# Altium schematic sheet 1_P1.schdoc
size 309 x 223 mm; Symbol: Sheet-Symbol_A4; Device: Sheet-Symbol_A4; Company: 嘉立创EDA; Version: V1.0; Page Size: A4; @Project Name: piezoAmpBoard; @Page Count: 1; @Update Date: 2024-03-09; @Create Date: 2024-03-08; @Schematic Name: Schematic1; @Page No: 1; @Page Name: P1; @Board Name: Board1; @Create Time: 23:16:16; @Update Time: 13:11:04
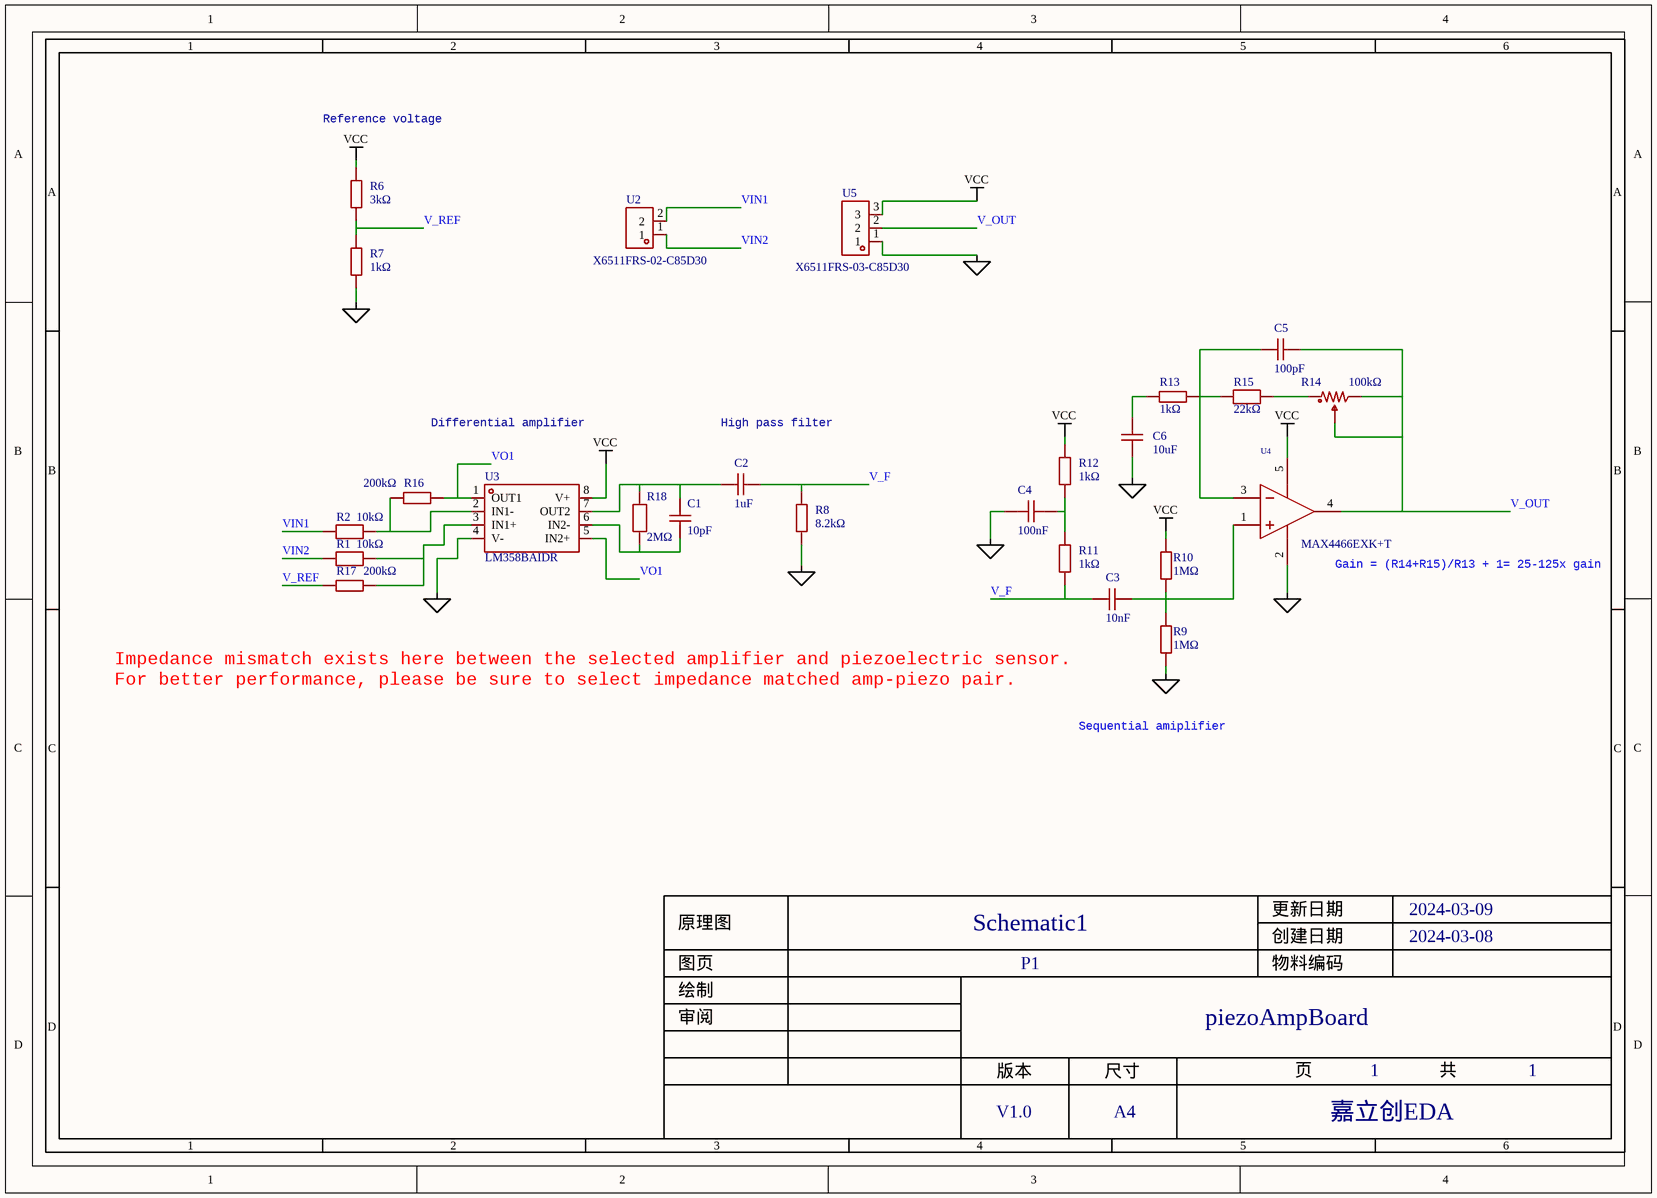
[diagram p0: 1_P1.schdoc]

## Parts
C1  10pF  [C0402]  (value not drawn)
C2  1uF  [C0402]  (value not drawn)
C3  10nF  [C0402]  (value not drawn)
C4  100nF  [C0402]  (value not drawn)
C5  100pF  [C0402]  (value not drawn)
C6  10uF  [C0402]  (value not drawn)
R1  10kΩ  [R0201]  (value not drawn)
R2  10kΩ  [R0201]  (value not drawn)
R6  3kΩ  [R0402]  (value not drawn)
R7  1kΩ  [R0402]  (value not drawn)
R8  8.2kΩ  [R0402]  (value not drawn)
R9  1MΩ  [R0201]  (value not drawn)
R10  1MΩ  [R0201]  (value not drawn)
R11  1kΩ  [R0201]  (value not drawn)
R12  1kΩ  [R0201]  (value not drawn)
R13  1kΩ  [R0201]  (value not drawn)
R14  100kΩ  [RES-ADJ-SMD_TC33X-2-104E]  (value not drawn)
R15  22kΩ  [R0201]  (value not drawn)
R16  200kΩ  [R0201]  (value not drawn)
R17  200kΩ  [R0201]  (value not drawn)
R18  2MΩ  [R0201]  (value not drawn)
U2  X6511FRS-02-C85D30  [HDR-SMD_2P-P2.54-H-F-L11.5]  (value not drawn)
U3  LM358BAIDR  [SOIC-8_L4.9-W3.9-P1.27-LS6.0-BL]  (value not drawn)
U4  MAX4466EXK+T  [SC-70-5_L2.0-W1.3-P0.65-LS2.1-BR]  (value not drawn)
U5  X6511FRS-03-C85D30  [HDR-SMD_3P-P2.54-H-F-L11.5]  (value not drawn)

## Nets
AGND: C4.1 C6.1 R7.1 R8.1 R9.1 U3.4(V-) U4.2(GND) U5.1
VCC: R6.2 R10.2 R12.2 U3.8(V+) U4.5(VCC) U5.3
V_F: C2.2 C3.1 R8.2 R11.1
V_OUT: C5.2 R14.2 R14.3 U4.4(OUT) U5.2
V_REF: R6.1 R7.2 R17.1
VIN1: R2.1 U2.2
VIN2: R1.1 U2.1
VO1: R16.2 U3.1(OUT1) U3.5(IN2+)
NetC1_1: C1.1 R18.1 U3.6(IN2-)
NetC1_2: C1.2 C2.1 R18.2 U3.7(OUT2)
NetC3_2: C3.2 R9.2 R10.1 U4.1(IN+)
NetC4_2: C4.2 R11.2 R12.1
NetC5_1: C5.1 R13.2 R15.1 U4.3(IN-)
NetC6_2: C6.2 R13.1
NetR1_2: R1.2 R17.2 U3.3(IN1+)
NetR2_2: R2.2 R16.1 U3.2(IN1-)
NetR14_1: R14.1 R15.2

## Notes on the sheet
- Reference voltage
- Differential amplifier
- High pass filter
- (near U4) Gain = (R14+R15)/R13 + 1= 25-125x gain
- Impedance mismatch exists here between the selected amplifier and piezoelectric sensor.
  For better performance, please be sure to select impedance matched amp-piezo pair.
- Sequential amiplifier

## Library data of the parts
C1 = CC0402JRNPO9BN100: 容值:10pF;精度:±5%;额定电压:50V;材质(温度系数):NP0;; Manufacturer: YAGEO(国巨); Add into BOM: yes; Tolerance: ±5%; Voltage Rated: 50V; Temperature Coefficient: NP0
C2 = CL05A105KP5NNNC: 容值:1uF;精度:±10%;额定电压:10V;材质(温度系数):X5R;; Manufacturer: SAMSUNG(三星); Add into BOM: yes; Tolerance: ±10%; Voltage Rated: 10V; Temperature Coefficient: X5R
C3 = CC0402KRX7R9BB103: 容值:10nF;精度:±10%;额定电压:50V;材质(温度系数):X7R;; Manufacturer: YAGEO(国巨); Add into BOM: yes; Tolerance: ±10%; Voltage Rated: 50V; Temperature Coefficient: X7R
C4 = CC0402KRX7R7BB104: 容值:100nF;精度:±10%;额定电压:16V;材质(温度系数):X7R;; Manufacturer: YAGEO(国巨); Add into BOM: yes; Tolerance: ±10%; Voltage Rated: 16V; Temperature Coefficient: X7R
C5 = GRM1555C1H101JA01D: 容值:100pF;精度:±5%;额定电压:50V;材质(温度系数):C0G;; Manufacturer: muRata(村田); Add into BOM: yes; Tolerance: ±5%; Voltage Rated: 50V; Temperature Coefficient: C0G
C6 = GRM155R60J106ME44D: 容值:10uF;精度:±20%;额定电压:6.3V;材质(温度系数):X5R;; Manufacturer: muRata(村田); Add into BOM: yes; Tolerance: ±20%; Voltage Rated: 6.3V; Temperature Coefficient: X5R
R1 R2 = 0201WMF1002TEE: 电阻类型:厚膜电阻;阻值:10kΩ;精度:±1%;功率:50mW;最大工作电压:25V;温度系数:±200ppm/℃;; Manufacturer: UNI-ROYAL(厚声); Add into BOM: yes; Tolerance: ±1%; Power(Watts): 50mW; Overload Voltage (Max): 25V
R6 = 0402WGF3001TCE: 电阻类型:厚膜电阻;阻值:3kΩ;精度:±1%;功率:62.5mW;最大工作电压:50V;温度系数:±100ppm/℃;; Manufacturer: UNI-ROYAL(厚声); Add into BOM: yes; Tolerance: ±1%; Power(Watts): 62.5mW; Overload Voltage (Max): 50V
R7 = 0402WGF1001TCE: 电阻类型:厚膜电阻;阻值:1kΩ;精度:±1%;功率:62.5mW;最大工作电压:50V;温度系数:±100ppm/℃;; Manufacturer: UNI-ROYAL(厚声); Add into BOM: yes; Tolerance: ±1%; Power(Watts): 62.5mW; Overload Voltage (Max): 50V
R8 = 0402WGF8201TCE: 电阻类型:厚膜电阻;阻值:8.2kΩ;精度:±1%;功率:62.5mW;最大工作电压:50V;温度系数:±100ppm/℃;; Manufacturer: UNI-ROYAL(厚声); Add into BOM: yes; Tolerance: ±1%; Power(Watts): 62.5mW; Overload Voltage (Max): 50V
R9 R10 = RC0201FR-071ML: 电阻类型:厚膜电阻;阻值:1MΩ;精度:±1%;功率:50mW;最大工作电压:25V;温度系数:±200ppm/℃;; Manufacturer: YAGEO(国巨); Add into BOM: yes; Tolerance: ±1%; Power(Watts): 50mW; Overload Voltage (Max): 25V
R11-R13 = 0201WMF1001TEE: 电阻类型:厚膜电阻;阻值:1kΩ;精度:±1%;功率:50mW;最大工作电压:25V;温度系数:±200ppm/℃;; Manufacturer: UNI-ROYAL(厚声); Add into BOM: yes; Tolerance: ±1%; Power(Watts): 50mW; Overload Voltage (Max): 25V
R14 = TC33X-2-104E: 阻值:100kΩ;精度:±25%;功率:150mW;温度系数:±250ppm/℃;; Manufacturer: BOURNS; Add into BOM: yes; Tolerance: ±25%; Power(Watts): 150mW; Turns: 1
R15 = RC0201FR-0722KL: 电阻类型:厚膜电阻;阻值:22kΩ;精度:±1%;功率:50mW;最大工作电压:25V;温度系数:±200ppm/℃;; Manufacturer: YAGEO(国巨); Add into BOM: yes; Tolerance: ±1%; Power(Watts): 50mW; Overload Voltage (Max): 25V
R16 R17 = RC0201FR-07200KL: 电阻类型:厚膜电阻;阻值:200kΩ;精度:±1%;功率:50mW;最大工作电压:25V;温度系数:±200ppm/℃;; Manufacturer: YAGEO(国巨); Add into BOM: yes; Tolerance: ±1%; Power(Watts): 50mW; Overload Voltage (Max): 25V
R18 = 0201WMF2004TEE: 电阻类型:厚膜电阻;阻值:2MΩ;精度:±1%;功率:50mW;最大工作电压:25V;温度系数:±200ppm/℃;; Manufacturer: UNI-ROYAL(厚声); Add into BOM: yes; Tolerance: ±1%; Power(Watts): 50mW; Overload Voltage (Max): 25V
U2 = X6511FRS-02-C85D30: 插孔结构:1x2P;间距:2.54mm;安装类型:卧贴;排数:单排;总孔位数:2P;塑高:8.5mm;; Manufacturer: XKB Connectivity(中国星坤); Add into BOM: yes; Holes Structure: 1x2P; Pitch: 2.54mm; Number of Holes: 2P
U3 = LM358BAIDR: 放大器数:双路;增益带宽积(GBP):1.2MHz;输入偏置电流(Ib):10nA;压摆率(SR):0.5V/us;带宽(-3db):-;; Manufacturer: TI(德州仪器); Add into BOM: yes; Number of Circuits: 双路; Gain Bandwidth Product(GBP): 1.2MHz; Current - Input Bias(Ib): 10nA; Output Current: 40mA
U4 = MAX4466EXK+T: 功放类型:-;扬声器通道数:单声道;输出功率:-;静态电流(Iq):-;; Manufacturer: ADI(亚德诺)/MAXIM(美信); Add into BOM: yes; Speaker Channels: 单声道; Supply Voltage: 2.4V~5.5V
U5 = X6511FRS-03-C85D30: 插孔结构:1x3P;间距:2.54mm;安装类型:卧贴;排数:单排;总孔位数:3P;塑高:8.5mm;; Manufacturer: XKB Connectivity(中国星坤); Add into BOM: yes; Holes Structure: 1x3P; Pitch: 2.54mm; Number of Holes: 3P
